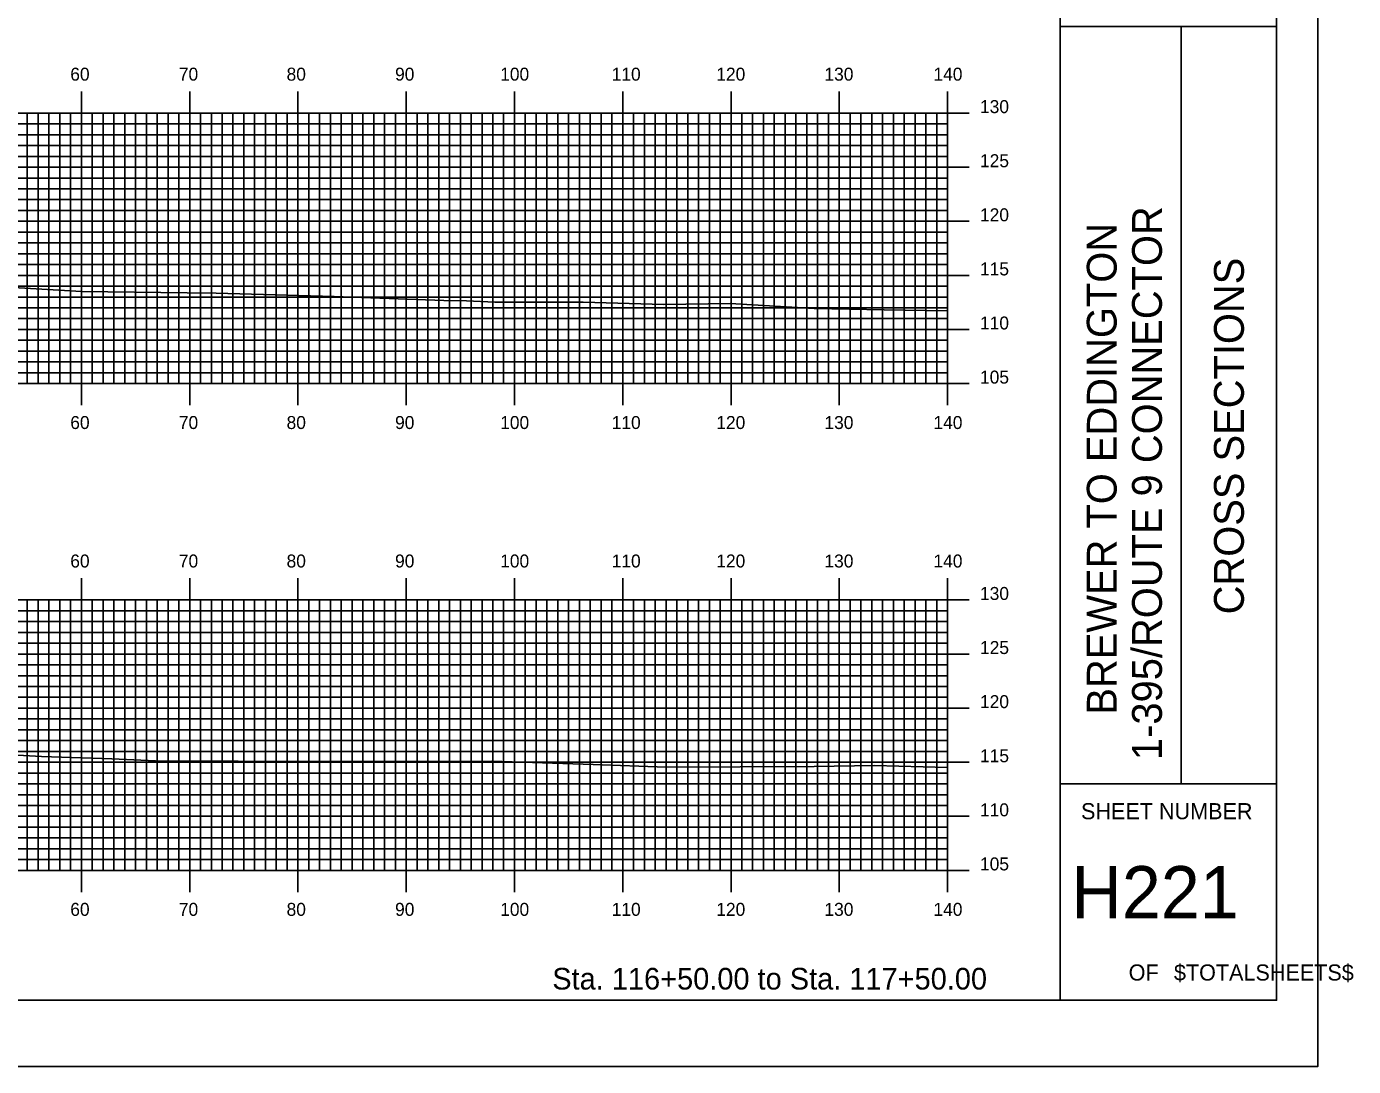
# Model space of a CAD drawing. Extents: x 1771235 to 1771579, y 442591 to 442811.
# Drawn here: x 1771456 to 1771578.6, y 442590.5 to 442686.7 of the extents above; entities that cross this region are included whole.
import ezdxf

# ---------------------------------------------------------------- set-up
doc = ezdxf.new("R2010")
doc.units = 0
for name, color, linetype in [('BORDER', 7, 'Continuous'), ('H_V ANNOTATION', 7, 'Continuous'), ('MAJOR', 7, 'Continuous'), ('MINOR', 7, 'Continuous'), ('PLOT BOUNDARY', 7, 'Continuous'), ('S_Roadway_Centerline', 7, 'Continuous')]:
    doc.layers.add(name, color=color, linetype=linetype)

msp = doc.modelspace()

# ---------------------------------------------------------------- linework, layer by layer
at = {"layer": 'BORDER'}
for p, q in [((1771551.47, 442596.67), (1771551.47, 442806.67)), ((1771551.47, 442686.67), (1771571.47, 442686.67)), ((1771562.65, 442616.67), (1771562.65, 442686.67)), ((1771551.47, 442616.67), (1771571.47, 442616.67))]:
    msp.add_line(p, q, dxfattribs=at)
msp.add_lwpolyline([(1771251.47, 442596.67), (1771571.47, 442596.67), (1771571.47, 442806.67), (1771251.47, 442806.67)], close=True, dxfattribs=at)
at = {"layer": 'MAJOR'}
for p, q in [((1771461.07, 442680.67), (1771461.07, 442678.67)), ((1771471.07, 442680.67), (1771471.07, 442678.67)), ((1771481.07, 442680.67), (1771481.07, 442678.67)), ((1771491.07, 442680.67), (1771491.07, 442678.67)), ((1771501.07, 442680.67), (1771501.07, 442678.67)), ((1771511.07, 442680.67), (1771511.07, 442678.67)), ((1771521.07, 442680.67), (1771521.07, 442678.67)), ((1771531.07, 442680.67), (1771531.07, 442678.67)), ((1771541.07, 442680.67), (1771541.07, 442678.67)), ((1771261.07, 442678.67), (1771541.07, 442678.67)), ((1771261.07, 442678.67), (1771541.07, 442678.67)), ((1771461.07, 442653.67), (1771461.07, 442678.67)), ((1771471.07, 442653.67), (1771471.07, 442678.67)), ((1771481.07, 442653.67), (1771481.07, 442678.67)), ((1771491.07, 442653.67), (1771491.07, 442678.67)), ((1771501.07, 442653.67), (1771501.07, 442678.67)), ((1771511.07, 442653.67), (1771511.07, 442678.67)), ((1771521.07, 442653.67), (1771521.07, 442678.67)), ((1771531.07, 442653.67), (1771531.07, 442678.67)), ((1771543.07, 442678.67), (1771539.06, 442678.67)), ((1771541.07, 442653.67), (1771541.07, 442678.67)), ((1771541.07, 442653.67), (1771541.07, 442678.67)), ((1771261.07, 442673.67), (1771541.07, 442673.67)), ((1771543.07, 442673.67), (1771539.06, 442673.67)), ((1771261.07, 442668.67), (1771541.07, 442668.67)), ((1771543.07, 442668.67), (1771539.06, 442668.67)), ((1771261.07, 442663.67), (1771541.07, 442663.67)), ((1771543.07, 442663.67), (1771539.06, 442663.67)), ((1771261.07, 442658.67), (1771541.07, 442658.67)), ((1771543.07, 442658.67), (1771539.06, 442658.67)), ((1771261.07, 442653.67), (1771541.07, 442653.67)), ((1771261.07, 442653.67), (1771541.07, 442653.67)), ((1771461.07, 442651.66), (1771461.07, 442653.67)), ((1771471.07, 442651.66), (1771471.07, 442653.67)), ((1771481.07, 442651.66), (1771481.07, 442653.67)), ((1771491.07, 442651.66), (1771491.07, 442653.67)), ((1771501.07, 442651.66), (1771501.07, 442653.67)), ((1771511.07, 442651.66), (1771511.07, 442653.67)), ((1771521.07, 442651.66), (1771521.07, 442653.67)), ((1771531.07, 442651.66), (1771531.07, 442653.67)), ((1771543.07, 442653.67), (1771539.06, 442653.67)), ((1771541.07, 442651.66), (1771541.07, 442653.67)), ((1771461.07, 442635.67), (1771461.07, 442633.67)), ((1771471.07, 442635.67), (1771471.07, 442633.67)), ((1771481.07, 442635.67), (1771481.07, 442633.67)), ((1771491.07, 442635.67), (1771491.07, 442633.67)), ((1771501.07, 442635.67), (1771501.07, 442633.67)), ((1771511.07, 442635.67), (1771511.07, 442633.67)), ((1771521.07, 442635.67), (1771521.07, 442633.67)), ((1771531.07, 442635.67), (1771531.07, 442633.67)), ((1771541.07, 442635.67), (1771541.07, 442633.67)), ((1771261.07, 442633.67), (1771541.07, 442633.67)), ((1771261.07, 442633.67), (1771541.07, 442633.67)), ((1771461.07, 442608.67), (1771461.07, 442633.67)), ((1771471.07, 442608.67), (1771471.07, 442633.67)), ((1771481.07, 442608.67), (1771481.07, 442633.67)), ((1771491.07, 442608.67), (1771491.07, 442633.67)), ((1771501.07, 442608.67), (1771501.07, 442633.67)), ((1771511.07, 442608.67), (1771511.07, 442633.67)), ((1771521.07, 442608.67), (1771521.07, 442633.67)), ((1771531.07, 442608.67), (1771531.07, 442633.67)), ((1771543.07, 442633.67), (1771539.06, 442633.67)), ((1771541.07, 442608.67), (1771541.07, 442633.67)), ((1771541.07, 442608.67), (1771541.07, 442633.67)), ((1771261.07, 442628.67), (1771541.07, 442628.67)), ((1771543.07, 442628.67), (1771539.06, 442628.67)), ((1771261.07, 442623.67), (1771541.07, 442623.67)), ((1771543.07, 442623.67), (1771539.06, 442623.67)), ((1771261.07, 442618.67), (1771541.07, 442618.67)), ((1771543.07, 442618.67), (1771539.06, 442618.67)), ((1771261.07, 442613.67), (1771541.07, 442613.67)), ((1771543.07, 442613.67), (1771539.06, 442613.67)), ((1771261.07, 442608.67), (1771541.07, 442608.67)), ((1771261.07, 442608.67), (1771541.07, 442608.67)), ((1771461.07, 442606.66), (1771461.07, 442608.67)), ((1771471.07, 442606.66), (1771471.07, 442608.67)), ((1771481.07, 442606.66), (1771481.07, 442608.67)), ((1771491.07, 442606.66), (1771491.07, 442608.67)), ((1771501.07, 442606.66), (1771501.07, 442608.67)), ((1771511.07, 442606.66), (1771511.07, 442608.67)), ((1771521.07, 442606.66), (1771521.07, 442608.67)), ((1771531.07, 442606.66), (1771531.07, 442608.67)), ((1771543.07, 442608.67), (1771539.06, 442608.67)), ((1771541.07, 442606.66), (1771541.07, 442608.67))]:
    msp.add_line(p, q, dxfattribs=at)
at = {"layer": 'MINOR'}
for p, q in [((1771456.07, 442653.67), (1771456.07, 442678.67)), ((1771457.07, 442653.67), (1771457.07, 442678.67)), ((1771458.07, 442653.67), (1771458.07, 442678.67)), ((1771459.07, 442653.67), (1771459.07, 442678.67)), ((1771460.07, 442653.67), (1771460.07, 442678.67)), ((1771462.07, 442653.67), (1771462.07, 442678.67)), ((1771463.07, 442653.67), (1771463.07, 442678.67)), ((1771464.07, 442653.67), (1771464.07, 442678.67)), ((1771465.07, 442653.67), (1771465.07, 442678.67)), ((1771466.07, 442653.67), (1771466.07, 442678.67)), ((1771467.07, 442653.67), (1771467.07, 442678.67)), ((1771468.07, 442653.67), (1771468.07, 442678.67)), ((1771469.07, 442653.67), (1771469.07, 442678.67)), ((1771470.07, 442653.67), (1771470.07, 442678.67)), ((1771472.07, 442653.67), (1771472.07, 442678.67)), ((1771473.07, 442653.67), (1771473.07, 442678.67)), ((1771474.07, 442653.67), (1771474.07, 442678.67)), ((1771475.07, 442653.67), (1771475.07, 442678.67)), ((1771476.07, 442653.67), (1771476.07, 442678.67)), ((1771477.07, 442653.67), (1771477.07, 442678.67)), ((1771478.07, 442653.67), (1771478.07, 442678.67)), ((1771479.07, 442653.67), (1771479.07, 442678.67)), ((1771480.07, 442653.67), (1771480.07, 442678.67)), ((1771482.07, 442653.67), (1771482.07, 442678.67)), ((1771483.07, 442653.67), (1771483.07, 442678.67)), ((1771484.07, 442653.67), (1771484.07, 442678.67)), ((1771485.07, 442653.67), (1771485.07, 442678.67)), ((1771486.07, 442653.67), (1771486.07, 442678.67)), ((1771487.07, 442653.67), (1771487.07, 442678.67)), ((1771488.07, 442653.67), (1771488.07, 442678.67)), ((1771489.07, 442653.67), (1771489.07, 442678.67)), ((1771490.07, 442653.67), (1771490.07, 442678.67)), ((1771492.07, 442653.67), (1771492.07, 442678.67)), ((1771493.07, 442653.67), (1771493.07, 442678.67)), ((1771494.07, 442653.67), (1771494.07, 442678.67)), ((1771495.07, 442653.67), (1771495.07, 442678.67)), ((1771496.07, 442653.67), (1771496.07, 442678.67)), ((1771497.07, 442653.67), (1771497.07, 442678.67)), ((1771498.07, 442653.67), (1771498.07, 442678.67)), ((1771499.07, 442653.67), (1771499.07, 442678.67)), ((1771500.07, 442653.67), (1771500.07, 442678.67)), ((1771502.07, 442653.67), (1771502.07, 442678.67)), ((1771503.07, 442653.67), (1771503.07, 442678.67)), ((1771504.07, 442653.67), (1771504.07, 442678.67)), ((1771505.07, 442653.67), (1771505.07, 442678.67)), ((1771506.07, 442653.67), (1771506.07, 442678.67)), ((1771507.07, 442653.67), (1771507.07, 442678.67)), ((1771508.07, 442653.67), (1771508.07, 442678.67)), ((1771509.07, 442653.67), (1771509.07, 442678.67)), ((1771510.07, 442653.67), (1771510.07, 442678.67)), ((1771512.07, 442653.67), (1771512.07, 442678.67)), ((1771513.07, 442653.67), (1771513.07, 442678.67)), ((1771514.07, 442653.67), (1771514.07, 442678.67)), ((1771515.07, 442653.67), (1771515.07, 442678.67)), ((1771516.07, 442653.67), (1771516.07, 442678.67)), ((1771517.07, 442653.67), (1771517.07, 442678.67)), ((1771518.07, 442653.67), (1771518.07, 442678.67)), ((1771519.07, 442653.67), (1771519.07, 442678.67)), ((1771520.07, 442653.67), (1771520.07, 442678.67)), ((1771522.07, 442653.67), (1771522.07, 442678.67)), ((1771523.07, 442653.67), (1771523.07, 442678.67)), ((1771524.07, 442653.67), (1771524.07, 442678.67)), ((1771525.07, 442653.67), (1771525.07, 442678.67)), ((1771526.07, 442653.67), (1771526.07, 442678.67)), ((1771527.07, 442653.67), (1771527.07, 442678.67)), ((1771528.07, 442653.67), (1771528.07, 442678.67)), ((1771529.07, 442653.67), (1771529.07, 442678.67)), ((1771530.07, 442653.67), (1771530.07, 442678.67)), ((1771532.07, 442653.67), (1771532.07, 442678.67)), ((1771533.07, 442653.67), (1771533.07, 442678.67)), ((1771534.07, 442653.67), (1771534.07, 442678.67)), ((1771535.07, 442653.67), (1771535.07, 442678.67)), ((1771536.07, 442653.67), (1771536.07, 442678.67)), ((1771537.07, 442653.67), (1771537.07, 442678.67)), ((1771538.07, 442653.67), (1771538.07, 442678.67)), ((1771539.07, 442653.67), (1771539.07, 442678.67)), ((1771540.07, 442653.67), (1771540.07, 442678.67)), ((1771261.07, 442677.67), (1771541.07, 442677.67)), ((1771541.07, 442677.67), (1771539.06, 442677.67)), ((1771261.07, 442676.67), (1771541.07, 442676.67)), ((1771261.07, 442675.67), (1771541.07, 442675.67)), ((1771541.07, 442676.67), (1771539.06, 442676.67)), ((1771541.07, 442675.67), (1771539.06, 442675.67)), ((1771261.07, 442674.67), (1771541.07, 442674.67)), ((1771541.07, 442674.67), (1771539.06, 442674.67)), ((1771261.07, 442672.67), (1771541.07, 442672.67)), ((1771541.07, 442672.67), (1771539.06, 442672.67)), ((1771261.07, 442671.67), (1771541.07, 442671.67)), ((1771541.07, 442671.67), (1771539.06, 442671.67)), ((1771261.07, 442670.67), (1771541.07, 442670.67)), ((1771261.07, 442669.67), (1771541.07, 442669.67)), ((1771541.07, 442670.67), (1771539.06, 442670.67)), ((1771541.07, 442669.67), (1771539.06, 442669.67)), ((1771261.07, 442667.67), (1771541.07, 442667.67)), ((1771541.07, 442667.67), (1771539.06, 442667.67)), ((1771261.07, 442666.67), (1771541.07, 442666.67)), ((1771541.07, 442666.67), (1771539.06, 442666.67)), ((1771261.07, 442665.67), (1771541.07, 442665.67)), ((1771261.07, 442664.67), (1771541.07, 442664.67)), ((1771541.07, 442665.67), (1771539.06, 442665.67)), ((1771541.07, 442664.67), (1771539.06, 442664.67)), ((1771261.07, 442662.67), (1771541.07, 442662.67)), ((1771541.07, 442662.67), (1771539.06, 442662.67)), ((1771261.07, 442661.67), (1771541.07, 442661.67)), ((1771541.07, 442661.67), (1771539.06, 442661.67)), ((1771261.07, 442660.67), (1771541.07, 442660.67)), ((1771541.07, 442660.67), (1771539.06, 442660.67)), ((1771261.07, 442659.67), (1771541.07, 442659.67)), ((1771541.07, 442659.67), (1771539.06, 442659.67)), ((1771261.07, 442657.67), (1771541.07, 442657.67)), ((1771541.07, 442657.67), (1771539.06, 442657.67)), ((1771261.07, 442656.67), (1771541.07, 442656.67)), ((1771541.07, 442656.67), (1771539.06, 442656.67)), ((1771261.07, 442655.67), (1771541.07, 442655.67)), ((1771541.07, 442655.67), (1771539.06, 442655.67)), ((1771261.07, 442654.67), (1771541.07, 442654.67)), ((1771541.07, 442654.67), (1771539.06, 442654.67)), ((1771456.07, 442608.67), (1771456.07, 442633.67)), ((1771457.07, 442608.67), (1771457.07, 442633.67)), ((1771458.07, 442608.67), (1771458.07, 442633.67)), ((1771459.07, 442608.67), (1771459.07, 442633.67)), ((1771460.07, 442608.67), (1771460.07, 442633.67)), ((1771462.07, 442608.67), (1771462.07, 442633.67)), ((1771463.07, 442608.67), (1771463.07, 442633.67)), ((1771464.07, 442608.67), (1771464.07, 442633.67)), ((1771465.07, 442608.67), (1771465.07, 442633.67)), ((1771466.07, 442608.67), (1771466.07, 442633.67)), ((1771467.07, 442608.67), (1771467.07, 442633.67)), ((1771468.07, 442608.67), (1771468.07, 442633.67)), ((1771469.07, 442608.67), (1771469.07, 442633.67)), ((1771470.07, 442608.67), (1771470.07, 442633.67)), ((1771472.07, 442608.67), (1771472.07, 442633.67)), ((1771473.07, 442608.67), (1771473.07, 442633.67)), ((1771474.07, 442608.67), (1771474.07, 442633.67)), ((1771475.07, 442608.67), (1771475.07, 442633.67)), ((1771476.07, 442608.67), (1771476.07, 442633.67)), ((1771477.07, 442608.67), (1771477.07, 442633.67)), ((1771478.07, 442608.67), (1771478.07, 442633.67)), ((1771479.07, 442608.67), (1771479.07, 442633.67)), ((1771480.07, 442608.67), (1771480.07, 442633.67)), ((1771482.07, 442608.67), (1771482.07, 442633.67)), ((1771483.07, 442608.67), (1771483.07, 442633.67)), ((1771484.07, 442608.67), (1771484.07, 442633.67)), ((1771485.07, 442608.67), (1771485.07, 442633.67)), ((1771486.07, 442608.67), (1771486.07, 442633.67)), ((1771487.07, 442608.67), (1771487.07, 442633.67)), ((1771488.07, 442608.67), (1771488.07, 442633.67)), ((1771489.07, 442608.67), (1771489.07, 442633.67)), ((1771490.07, 442608.67), (1771490.07, 442633.67)), ((1771492.07, 442608.67), (1771492.07, 442633.67)), ((1771493.07, 442608.67), (1771493.07, 442633.67)), ((1771494.07, 442608.67), (1771494.07, 442633.67)), ((1771495.07, 442608.67), (1771495.07, 442633.67)), ((1771496.07, 442608.67), (1771496.07, 442633.67)), ((1771497.07, 442608.67), (1771497.07, 442633.67)), ((1771498.07, 442608.67), (1771498.07, 442633.67)), ((1771499.07, 442608.67), (1771499.07, 442633.67)), ((1771500.07, 442608.67), (1771500.07, 442633.67)), ((1771502.07, 442608.67), (1771502.07, 442633.67)), ((1771503.07, 442608.67), (1771503.07, 442633.67)), ((1771504.07, 442608.67), (1771504.07, 442633.67)), ((1771505.07, 442608.67), (1771505.07, 442633.67)), ((1771506.07, 442608.67), (1771506.07, 442633.67)), ((1771507.07, 442608.67), (1771507.07, 442633.67)), ((1771508.07, 442608.67), (1771508.07, 442633.67)), ((1771509.07, 442608.67), (1771509.07, 442633.67)), ((1771510.07, 442608.67), (1771510.07, 442633.67)), ((1771512.07, 442608.67), (1771512.07, 442633.67)), ((1771513.07, 442608.67), (1771513.07, 442633.67)), ((1771514.07, 442608.67), (1771514.07, 442633.67)), ((1771515.07, 442608.67), (1771515.07, 442633.67)), ((1771516.07, 442608.67), (1771516.07, 442633.67)), ((1771517.07, 442608.67), (1771517.07, 442633.67)), ((1771518.07, 442608.67), (1771518.07, 442633.67)), ((1771519.07, 442608.67), (1771519.07, 442633.67)), ((1771520.07, 442608.67), (1771520.07, 442633.67)), ((1771522.07, 442608.67), (1771522.07, 442633.67)), ((1771523.07, 442608.67), (1771523.07, 442633.67)), ((1771524.07, 442608.67), (1771524.07, 442633.67)), ((1771525.07, 442608.67), (1771525.07, 442633.67)), ((1771526.07, 442608.67), (1771526.07, 442633.67)), ((1771527.07, 442608.67), (1771527.07, 442633.67)), ((1771528.07, 442608.67), (1771528.07, 442633.67)), ((1771529.07, 442608.67), (1771529.07, 442633.67)), ((1771530.07, 442608.67), (1771530.07, 442633.67)), ((1771532.07, 442608.67), (1771532.07, 442633.67)), ((1771533.07, 442608.67), (1771533.07, 442633.67)), ((1771534.07, 442608.67), (1771534.07, 442633.67)), ((1771535.07, 442608.67), (1771535.07, 442633.67)), ((1771536.07, 442608.67), (1771536.07, 442633.67)), ((1771537.07, 442608.67), (1771537.07, 442633.67)), ((1771538.07, 442608.67), (1771538.07, 442633.67)), ((1771539.07, 442608.67), (1771539.07, 442633.67)), ((1771540.07, 442608.67), (1771540.07, 442633.67)), ((1771261.07, 442632.67), (1771541.07, 442632.67)), ((1771261.07, 442631.67), (1771541.07, 442631.67)), ((1771541.07, 442632.67), (1771539.06, 442632.67)), ((1771541.07, 442631.67), (1771539.06, 442631.67)), ((1771261.07, 442630.67), (1771541.07, 442630.67)), ((1771541.07, 442630.67), (1771539.06, 442630.67)), ((1771261.07, 442629.67), (1771541.07, 442629.67)), ((1771541.07, 442629.67), (1771539.06, 442629.67)), ((1771261.07, 442627.67), (1771541.07, 442627.67)), ((1771261.07, 442626.67), (1771541.07, 442626.67)), ((1771541.07, 442627.67), (1771539.06, 442627.67)), ((1771541.07, 442626.67), (1771539.06, 442626.67)), ((1771261.07, 442625.67), (1771541.07, 442625.67)), ((1771541.07, 442625.67), (1771539.06, 442625.67)), ((1771261.07, 442624.67), (1771541.07, 442624.67)), ((1771541.07, 442624.67), (1771539.06, 442624.67)), ((1771261.07, 442622.67), (1771541.07, 442622.67)), ((1771541.07, 442622.67), (1771539.06, 442622.67)), ((1771261.07, 442621.67), (1771541.07, 442621.67)), ((1771261.07, 442620.67), (1771541.07, 442620.67)), ((1771541.07, 442621.67), (1771539.06, 442621.67)), ((1771541.07, 442620.67), (1771539.06, 442620.67)), ((1771261.07, 442619.67), (1771541.07, 442619.67)), ((1771541.07, 442619.67), (1771539.06, 442619.67)), ((1771261.07, 442617.67), (1771541.07, 442617.67)), ((1771541.07, 442617.67), (1771539.06, 442617.67)), ((1771261.07, 442616.67), (1771541.07, 442616.67)), ((1771261.07, 442615.67), (1771541.07, 442615.67)), ((1771541.07, 442616.67), (1771539.06, 442616.67)), ((1771541.07, 442615.67), (1771539.06, 442615.67)), ((1771261.07, 442614.67), (1771541.07, 442614.67)), ((1771541.07, 442614.67), (1771539.06, 442614.67)), ((1771261.07, 442612.67), (1771541.07, 442612.67)), ((1771541.07, 442612.67), (1771539.06, 442612.67)), ((1771261.07, 442611.67), (1771541.07, 442611.67)), ((1771541.07, 442611.67), (1771539.06, 442611.67)), ((1771261.07, 442610.67), (1771541.07, 442610.67)), ((1771261.07, 442609.67), (1771541.07, 442609.67)), ((1771541.07, 442610.67), (1771539.06, 442610.67)), ((1771541.07, 442609.67), (1771539.06, 442609.67))]:
    msp.add_line(p, q, dxfattribs=at)
at = {"layer": 'PLOT BOUNDARY'}
msp.add_lwpolyline([(1771235.28, 442590.55), (1771575.28, 442590.55), (1771575.28, 442810.55), (1771235.28, 442810.55)], close=True, dxfattribs=at)
at = {"layer": 'S_Roadway_Centerline'}
for points in [[(1771454.27, 442662.59), (1771461.08, 442662.17), (1771470.83, 442662.06), (1771473.53, 442662.02), (1771484.4, 442661.72), (1771494.55, 442661.34), (1771496.65, 442661.31), (1771499.25, 442661.2), (1771507.42, 442661.2), (1771514.88, 442660.97), (1771520.98, 442661.08), (1771528.76, 442660.61), (1771535.21, 442660.5), (1771541.07, 442660.4)], [(1771452.32, 442619.47), (1771457.37, 442619.19), (1771463.87, 442618.97), (1771468.6, 442618.78), (1771475.56, 442618.78), (1771486.83, 442618.75), (1771489.12, 442618.75), (1771498.97, 442618.77), (1771508.34, 442618.45), (1771515.07, 442618.21), (1771528.75, 442618.27), (1771534.31, 442618.37), (1771541.07, 442618.19)]]:
    msp.add_lwpolyline(points, dxfattribs=at)

# ---------------------------------------------------------------- texts
at = {"layer": 'BORDER'}
for s, p in [('1-395/ROUTE 9 CONNECTOR', (1771560.87, 442618.87)), ('BREWER TO EDDINGTON', (1771556.69, 442623.07)), ('CROSS SECTIONS', (1771568.44, 442632.34))]:
    msp.add_text(s, height=2.7557, rotation=90, dxfattribs=at).set_placement(p)
for s, height, p in [('SHEET NUMBER', 1.4905, (1771553.4, 442613.4)), ('H221', 4.839, (1771552.5, 442604.23)), ('OF', 1.491, (1771557.8, 442598.49)), ('$TOTALSHEETS$', 1.4905, (1771561.98, 442598.49))]:
    msp.add_text(s, height=height, dxfattribs=at).set_placement(p)
at = {"layer": 'H_V ANNOTATION'}
for s, height, p in [('60', 1.2, (1771460.04, 442681.67)), ('70', 1.2, (1771470.07, 442681.67)), ('80', 1.2, (1771480.02, 442681.67)), ('90', 1.2, (1771490.04, 442681.67)), ('100', 1.2, (1771499.75, 442681.67)), ('110', 1.2, (1771510.05, 442681.67)), ('120', 1.2, (1771519.71, 442681.67)), ('130', 1.2, (1771529.7, 442681.67)), ('140', 1.2, (1771539.77, 442681.67)), ('130', 1.2, (1771544.07, 442678.67)), ('125', 1.2, (1771544.07, 442673.67)), ('120', 1.2, (1771544.07, 442668.67)), ('115', 1.2, (1771544.07, 442663.67)), ('110', 1.2, (1771544.07, 442658.67)), ('105', 1.2, (1771544.07, 442653.67)), ('60', 1.2, (1771460.04, 442649.47)), ('70', 1.2, (1771470.07, 442649.47)), ('80', 1.2, (1771480.02, 442649.47)), ('90', 1.2, (1771490.04, 442649.47)), ('100', 1.2, (1771499.75, 442649.47)), ('110', 1.2, (1771510.05, 442649.47)), ('120', 1.2, (1771519.71, 442649.47)), ('130', 1.2, (1771529.7, 442649.47)), ('140', 1.2, (1771539.77, 442649.47)), ('60', 1.2, (1771460.04, 442636.67)), ('70', 1.2, (1771470.07, 442636.67)), ('80', 1.2, (1771480.02, 442636.67)), ('90', 1.2, (1771490.04, 442636.67)), ('100', 1.2, (1771499.75, 442636.67)), ('110', 1.2, (1771510.05, 442636.67)), ('120', 1.2, (1771519.71, 442636.67)), ('130', 1.2, (1771529.7, 442636.67)), ('140', 1.2, (1771539.77, 442636.67)), ('130', 1.2, (1771544.07, 442633.67)), ('125', 1.2, (1771544.07, 442628.67)), ('120', 1.2, (1771544.07, 442623.67)), ('115', 1.2, (1771544.07, 442618.67)), ('110', 1.2, (1771544.07, 442613.67)), ('105', 1.2, (1771544.07, 442608.67)), ('60', 1.2, (1771460.04, 442604.47)), ('70', 1.2, (1771470.07, 442604.47)), ('80', 1.2, (1771480.02, 442604.47)), ('90', 1.2, (1771490.04, 442604.47)), ('100', 1.2, (1771499.75, 442604.47)), ('110', 1.2, (1771510.05, 442604.47)), ('120', 1.2, (1771519.71, 442604.47)), ('130', 1.2, (1771529.7, 442604.47)), ('140', 1.2, (1771539.77, 442604.47)), ('Sta. 116+50.00 to Sta. 117+50.00', 2.0004, (1771504.56, 442597.66))]:
    msp.add_text(s, height=height, dxfattribs=at).set_placement(p)

doc.saveas('drawing.dxf')
